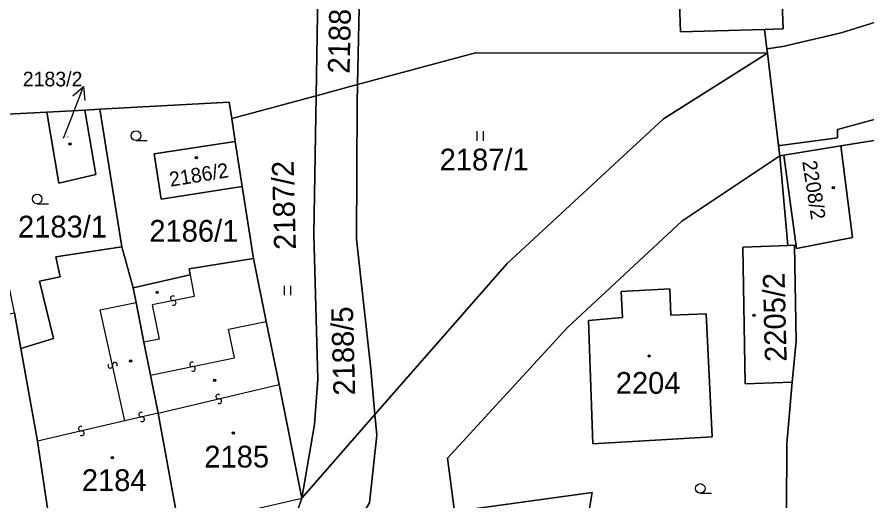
# Model space of a CAD drawing. Extents: x -596024 to -594475, y -1163820 to -1161957.
# Drawn here: x -595904.5 to -595838.1, y -1162929.2 to -1162891.5 of the extents above; entities that cross this region are included whole.
import ezdxf

# ---------------------------------------------------------------- set-up
doc = ezdxf.new("R2010")
doc.units = 0
for name, color, linetype in [('Level 1', 7, 'Continuous'), ('Level 13', 7, 'Continuous'), ('Level 3', 7, 'Continuous'), ('Level 4', 7, 'Continuous'), ('Level 5', 7, 'Continuous'), ('Level 57', 7, 'Continuous'), ('Level 60', 7, 'Continuous')]:
    doc.layers.add(name, color=color, linetype=linetype)

msp = doc.modelspace()

# ---------------------------------------------------------------- linework, layer by layer
at = {"layer": 'Level 1'}
for points in [[(-595689.67, -1162883.44), (-595700.86, -1162884.94), (-595711.82, -1162885.6), (-595719.78, -1162885.62), (-595739.76, -1162885.28), (-595774.42, -1162884.6), (-595796.1, -1162884.29), (-595801.08, -1162884.47), (-595808.03, -1162885.13), (-595817.92, -1162886.57), (-595821.84, -1162887.34), (-595827.71, -1162888.8), (-595840.08, -1162892.69), (-595844.64, -1162893.75), (-595845.9, -1162893.93)], [(-595846.86, -1162886.34), (-595844.86, -1162886.27), (-595844.63, -1162892.38), (-595846.09, -1162892.42)], [(-595846.09, -1162892.42), (-595852.65, -1162892.61), (-595852.84, -1162886.55), (-595846.86, -1162886.34)], [(-595880.94, -1162887.88), (-595880.94, -1162888.11), (-595881.1, -1162897.61)], [(-595877.88, -1162896.73), (-595877.69, -1162888.35)], [(-595845.9, -1162893.93), (-595846.09, -1162892.42)], [(-595844.98, -1162901.5), (-595844.85, -1162901.49), (-595840.38, -1162900.89), (-595840.38, -1162900.25), (-595836.17, -1162899.09), (-595829.54, -1162896.9), (-595823.17, -1162895.11), (-595816.86, -1162893.7), (-595811.96, -1162893.04)], [(-595845.85, -1162894.28), (-595868.65, -1162894.24), (-595877.88, -1162896.73)], [(-595845.85, -1162894.28), (-595845.9, -1162893.93)], [(-595876.51, -1162922.51), (-595866.18, -1162910.71), (-595853.97, -1162899.4), (-595845.85, -1162894.28)], [(-595844.98, -1162901.5), (-595845.85, -1162894.28)], [(-595877.88, -1162896.73), (-595881.1, -1162897.61)], [(-595876.51, -1162922.51), (-595876.84, -1162918.93), (-595877.95, -1162908.81), (-595877.91, -1162898.22), (-595877.88, -1162896.73)], [(-595898.01, -1162898.65), (-595887.89, -1162898.11), (-595887.69, -1162899.39)], [(-595881.1, -1162897.61), (-595887.69, -1162899.39)], [(-595881.1, -1162897.61), (-595881.28, -1162908.44), (-595880.98, -1162919.75), (-595881.22, -1162923.3), (-595882.23, -1162929.04)], [(-595902.15, -1162898.88), (-595907.82, -1162899.18)], [(-595902.15, -1162898.88), (-595901.19, -1162904.44), (-595898.3, -1162903.76), (-595899.18, -1162898.72)], [(-595899.18, -1162898.72), (-595902.15, -1162898.88)], [(-595898.01, -1162898.65), (-595899.18, -1162898.72)], [(-595898.01, -1162898.65), (-595896.28, -1162909.41)], [(-595840.12, -1162901.52), (-595822.87, -1162898.75)], [(-595887.42, -1162901.17), (-595887.69, -1162899.39)], [(-595886.87, -1162904.69), (-595893.2, -1162905.68), (-595893.75, -1162902.15), (-595887.42, -1162901.17)], [(-595887.42, -1162901.17), (-595886.87, -1162904.69)], [(-595844.88, -1162902.29), (-595844.98, -1162901.5)], [(-595844.56, -1162902.24), (-595840.12, -1162901.52)], [(-595840.12, -1162901.52), (-595839.22, -1162908.67), (-595843.59, -1162909.55), (-595844.56, -1162902.24)], [(-595844.88, -1162902.29), (-595844.56, -1162902.24)], [(-595844.88, -1162902.29), (-595852.53, -1162907.4), (-595861.47, -1162915.71), (-595870.83, -1162925.92), (-595870.3, -1162930.09), (-595859.54, -1162928.6), (-595860.31, -1162933.29), (-595852.92, -1162934.42), (-595851.41, -1162934.52)], [(-595844.27, -1162909.31), (-595844.88, -1162902.29)], [(-595886.87, -1162904.69), (-595886, -1162910.31)], [(-595896.28, -1162909.41), (-595901.43, -1162910.18), (-595901.1, -1162911.76), (-595902.72, -1162912.09), (-595901.62, -1162916.57), (-595904.16, -1162917.34)], [(-595895.4, -1162912.6), (-595896.28, -1162909.41)], [(-595843.91, -1162919.98), (-595847.58, -1162920.12), (-595847.77, -1162909.44), (-595844.27, -1162909.31)], [(-595843.91, -1162919.98), (-595843.62, -1162916.78), (-595843.75, -1162909.29), (-595844.27, -1162909.31)], [(-595886, -1162910.31), (-595891.03, -1162911.14), (-595890.95, -1162911.6)], [(-595885, -1162915.24), (-595886, -1162910.31)], [(-595895.4, -1162912.6), (-595890.95, -1162911.6)], [(-595895.17, -1162913.77), (-595895.4, -1162912.6)], [(-595859.84, -1162915.16), (-595859.49, -1162924.81), (-595850.18, -1162924.26), (-595850.63, -1162914.64), (-595853.39, -1162914.76), (-595853.48, -1162912.7), (-595857.27, -1162912.91), (-595857.18, -1162914.94), (-595859.84, -1162915.16)], [(-595894.55, -1162916.85), (-595895.17, -1162913.77)], [(-595904.66, -1162914.56), (-595904.16, -1162917.34)], [(-595883.99, -1162920.17), (-595885, -1162915.24)], [(-595904.16, -1162917.34), (-595902.86, -1162924.58)], [(-595894.03, -1162919.44), (-595894.55, -1162916.85)], [(-595893.43, -1162922.4), (-595894.03, -1162919.44)], [(-595843.91, -1162919.98), (-595844.34, -1162924.77), (-595844.4, -1162935.47)], [(-595883.99, -1162920.17), (-595882.23, -1162929.04)], [(-595892.11, -1162982.55), (-595893.66, -1162967.36), (-595893.27, -1162958.56), (-595891.77, -1162951.47), (-595888.99, -1162944.59), (-595880.96, -1162936.06), (-595876.94, -1162929.4), (-595876.36, -1162924.12), (-595876.51, -1162922.51)], [(-595893.43, -1162922.4), (-595891.83, -1162931.26)], [(-595876.51, -1162922.51), (-595882.23, -1162929.04)], [(-595901.53, -1162933.51), (-595902.86, -1162924.58)], [(-595882.57, -1162930.03), (-595882.23, -1162929.04)]]:
    msp.add_lwpolyline(points, dxfattribs=at)
at = {"layer": 'Level 13'}
for centre, start, end in [((-595892.295, -1162913.429), 48.23215, 280.82215), ((-595892.226, -1162913.791), 228.44661, 100.5446), ((-595897.18, -1162918.698), 139.85955, 11.95755), ((-595896.82, -1162918.621), 319.64509, 192.23509), ((-595890.796, -1162918.589), 49.01871, 281.11671), ((-595890.724, -1162918.95), 228.80425, 101.39425), ((-595888.751, -1162921.11), 50.66399, 282.76198), ((-595888.668, -1162921.469), 230.44953, 103.03953), ((-595894.78, -1162922.52), 50.10479, 282.69479), ((-595894.7, -1162922.88), 230.31924, 102.41724), ((-595899.491, -1162923.611), 50.20197, 282.79197), ((-595899.41, -1162923.97), 230.41643, 102.51442)]:
    msp.add_arc(centre, 0.184, start, end, dxfattribs=at)
at = {"layer": 'Level 3'}
for points in [[(-595890.95, -1162911.6), (-595890.63, -1162913.29), (-595893.9, -1162913.93), (-595893.37, -1162916.62), (-595894.55, -1162916.85)], [(-595896.04, -1162923), (-595897.96, -1162914.33), (-595895.17, -1162913.77)], [(-595894.03, -1162919.44), (-595887.48, -1162918.09), (-595887.94, -1162915.84), (-595885, -1162915.24)], [(-595893.43, -1162922.4), (-595883.99, -1162920.17)], [(-595893.43, -1162922.4), (-595896.04, -1162923)], [(-595896.04, -1162923), (-595902.86, -1162924.58)], [(-595891.83, -1162931.26), (-595882.23, -1162929.04)]]:
    msp.add_lwpolyline(points, dxfattribs=at)
at = {"layer": 'Level 5'}
for p, q in [((-595868.53, -1162901.115), (-595868.53, -1162900.364)), ((-595868.03, -1162901.115), (-595868.03, -1162900.364)), ((-595895.17, -1162901.1), (-595894.295, -1162901.1)), ((-595902.89, -1162906.04), (-595902.015, -1162906.04)), ((-595883.58, -1162913.195), (-595883.58, -1162912.444)), ((-595883.08, -1162913.195), (-595883.08, -1162912.444)), ((-595851.1, -1162928.66), (-595850.225, -1162928.66))]:
    msp.add_line(p, q, dxfattribs=at)
for centre, radius in [((-595895.17, -1162900.725), 0.375), ((-595900.32, -1162901.38), 0.09), ((-595900.32, -1162901.38), 0.0521), ((-595890.45, -1162902.45), 0.09), ((-595890.45, -1162902.45), 0.0521), ((-595840.71, -1162904.78), 0.09), ((-595840.71, -1162904.78), 0.0521), ((-595902.89, -1162905.665), 0.375), ((-595893.52, -1162912.96), 0.09), ((-595893.52, -1162912.96), 0.0521), ((-595846.9, -1162914.76), 0.09), ((-595846.9, -1162914.76), 0.0521), ((-595855.09, -1162917.93), 0.09), ((-595855.09, -1162917.93), 0.0521), ((-595895.59, -1162918.33), 0.09), ((-595895.59, -1162918.33), 0.0521), ((-595889.02, -1162919.85), 0.09), ((-595889.02, -1162919.85), 0.0521), ((-595887.58, -1162923.95), 0.09), ((-595887.58, -1162923.95), 0.0521), ((-595897.01, -1162925.89), 0.09), ((-595897.01, -1162925.89), 0.0521), ((-595851.1, -1162928.285), 0.375)]:
    msp.add_circle(centre, radius, dxfattribs=at)
at = {"layer": 'Level 57'}
for p, q in [((-595900.351, -1162899.669), (-595899.27, -1162896.87)), ((-595900.83, -1162900.91), (-595900.351, -1162899.669))]:
    msp.add_line(p, q, dxfattribs=at)
msp.add_lwpolyline([(-595900.097, -1162897.623), (-595899.27, -1162896.87), (-595899.164, -1162897.983)], dxfattribs=at)
at = {"layer": 'Level 60'}
for points in [[(-595880.94, -1162888.11), (-595881.1, -1162897.61), (-595887.69, -1162899.39), (-595887.89, -1162898.11), (-595898.01, -1162898.65), (-595899.18, -1162898.72), (-595902.15, -1162898.88), (-595907.82, -1162899.18), (-595923.48, -1162900.45), (-595934.83, -1162900.88), (-595942.06, -1162901.18), (-595961.43, -1162902), (-595966.37, -1162901.44), (-595978.21, -1162899.22), (-595980.89, -1162898.72), (-595991.69, -1162896.91), (-595991.71, -1162897.06), (-595998.18, -1162895.69), (-595999.71, -1162894.92), (-595997.34, -1162885.06)], [(-595827.71, -1162888.8), (-595840.08, -1162892.69), (-595844.64, -1162893.75), (-595845.9, -1162893.93), (-595846.09, -1162892.42), (-595844.63, -1162892.38), (-595844.86, -1162886.27)], [(-595836.17, -1162899.09), (-595840.38, -1162900.25), (-595840.38, -1162900.89), (-595844.85, -1162901.49), (-595844.98, -1162901.5), (-595845.85, -1162894.28), (-595845.9, -1162893.93), (-595844.64, -1162893.75), (-595840.08, -1162892.69), (-595827.71, -1162888.8)], [(-595876.94, -1162929.4), (-595876.36, -1162924.12), (-595876.51, -1162922.51), (-595866.18, -1162910.71), (-595853.97, -1162899.4), (-595845.85, -1162894.28), (-595844.98, -1162901.5), (-595844.88, -1162902.29), (-595852.53, -1162907.4), (-595861.47, -1162915.71), (-595870.83, -1162925.92), (-595870.3, -1162930.09), (-595859.54, -1162928.6), (-595860.31, -1162933.29)]]:
    msp.add_lwpolyline(points, dxfattribs=at)
for points in [[(-595852.84, -1162886.55), (-595852.65, -1162892.61), (-595846.09, -1162892.42), (-595845.9, -1162893.93), (-595845.85, -1162894.28), (-595868.65, -1162894.24), (-595877.88, -1162896.73), (-595877.69, -1162888.35), (-595846.93, -1162885.78), (-595846.86, -1162886.34)], [(-595852.65, -1162892.61), (-595852.84, -1162886.55), (-595846.86, -1162886.34), (-595844.86, -1162886.27), (-595844.63, -1162892.38), (-595846.09, -1162892.42)], [(-595880.94, -1162888.11), (-595880.94, -1162887.88), (-595877.66, -1162887.05), (-595877.69, -1162888.35), (-595877.88, -1162896.73), (-595881.1, -1162897.61)], [(-595844.85, -1162901.49), (-595840.38, -1162900.89), (-595840.38, -1162900.25), (-595836.17, -1162899.09), (-595829.54, -1162896.9), (-595823.17, -1162895.11), (-595816.86, -1162893.7), (-595811.96, -1162893.04), (-595811.88, -1162897.31), (-595822.87, -1162898.75), (-595840.12, -1162901.52), (-595844.56, -1162902.24), (-595844.88, -1162902.29), (-595844.98, -1162901.5)], [(-595853.97, -1162899.4), (-595866.18, -1162910.71), (-595876.51, -1162922.51), (-595876.84, -1162918.93), (-595877.95, -1162908.81), (-595877.91, -1162898.22), (-595877.88, -1162896.73), (-595868.65, -1162894.24), (-595845.85, -1162894.28)], [(-595880.98, -1162919.75), (-595881.28, -1162908.44), (-595881.1, -1162897.61), (-595877.88, -1162896.73), (-595877.91, -1162898.22), (-595877.95, -1162908.81), (-595876.84, -1162918.93), (-595876.51, -1162922.51), (-595882.23, -1162929.04), (-595881.22, -1162923.3)], [(-595896.28, -1162909.41), (-595898.01, -1162898.65), (-595887.89, -1162898.11), (-595887.69, -1162899.39), (-595887.42, -1162901.17), (-595893.75, -1162902.15), (-595893.2, -1162905.68), (-595886.87, -1162904.69), (-595886, -1162910.31), (-595891.03, -1162911.14), (-595890.95, -1162911.6), (-595895.4, -1162912.6)], [(-595881.28, -1162908.44), (-595880.98, -1162919.75), (-595881.22, -1162923.3), (-595882.23, -1162929.04), (-595883.99, -1162920.17), (-595885, -1162915.24), (-595886, -1162910.31), (-595886.87, -1162904.69), (-595887.42, -1162901.17), (-595887.69, -1162899.39), (-595881.1, -1162897.61)], [(-595904.16, -1162917.34), (-595904.66, -1162914.56), (-595907.82, -1162899.18), (-595902.15, -1162898.88), (-595901.19, -1162904.44), (-595898.3, -1162903.76), (-595899.18, -1162898.72), (-595898.01, -1162898.65), (-595896.28, -1162909.41), (-595901.43, -1162910.18), (-595901.1, -1162911.76), (-595902.72, -1162912.09), (-595901.62, -1162916.57)], [(-595901.19, -1162904.44), (-595902.15, -1162898.88), (-595899.18, -1162898.72), (-595898.3, -1162903.76)], [(-595822.36, -1162935.41), (-595844.4, -1162935.47), (-595844.34, -1162924.77), (-595843.91, -1162919.98), (-595843.62, -1162916.78), (-595843.75, -1162909.29), (-595844.27, -1162909.31), (-595844.88, -1162902.29), (-595844.56, -1162902.24), (-595843.59, -1162909.55), (-595839.22, -1162908.67), (-595840.12, -1162901.52), (-595822.87, -1162898.75), (-595822.76, -1162923.03), (-595822.37, -1162935.1)], [(-595893.2, -1162905.68), (-595893.75, -1162902.15), (-595887.42, -1162901.17), (-595886.87, -1162904.69)], [(-595840.12, -1162901.52), (-595839.22, -1162908.67), (-595843.59, -1162909.55), (-595844.56, -1162902.24)], [(-595847.58, -1162920.12), (-595843.91, -1162919.98), (-595844.34, -1162924.77), (-595844.4, -1162935.47), (-595851.41, -1162934.52), (-595852.92, -1162934.42), (-595860.31, -1162933.29), (-595859.54, -1162928.6), (-595870.3, -1162930.09), (-595870.83, -1162925.92), (-595861.47, -1162915.71), (-595852.53, -1162907.4), (-595844.88, -1162902.29), (-595844.27, -1162909.31), (-595847.77, -1162909.44)], [(-595901.53, -1162933.51), (-595902.86, -1162924.58), (-595904.16, -1162917.34), (-595901.62, -1162916.57), (-595902.72, -1162912.09), (-595901.1, -1162911.76), (-595901.43, -1162910.18), (-595896.28, -1162909.41), (-595895.4, -1162912.6), (-595895.17, -1162913.77), (-595894.55, -1162916.85), (-595894.03, -1162919.44), (-595893.43, -1162922.4), (-595891.83, -1162931.26), (-595891.12, -1162934.37), (-595901.08, -1162936.72)], [(-595843.91, -1162919.98), (-595847.58, -1162920.12), (-595847.77, -1162909.44), (-595844.27, -1162909.31), (-595843.75, -1162909.29), (-595843.62, -1162916.78)], [(-595882.57, -1162930.03), (-595885.98, -1162933.16), (-595891.12, -1162934.37), (-595891.83, -1162931.26), (-595893.43, -1162922.4), (-595894.03, -1162919.44), (-595894.55, -1162916.85), (-595895.17, -1162913.77), (-595895.4, -1162912.6), (-595890.95, -1162911.6), (-595891.03, -1162911.14), (-595886, -1162910.31), (-595885, -1162915.24), (-595883.99, -1162920.17), (-595882.23, -1162929.04)], [(-595859.84, -1162915.16), (-595859.49, -1162924.81), (-595850.18, -1162924.26), (-595850.63, -1162914.64), (-595853.39, -1162914.76), (-595853.48, -1162912.7), (-595857.27, -1162912.91), (-595857.18, -1162914.94)], [(-595859.49, -1162924.81), (-595859.84, -1162915.16), (-595857.18, -1162914.94), (-595857.27, -1162912.91), (-595853.48, -1162912.7), (-595853.39, -1162914.76), (-595850.63, -1162914.64), (-595850.18, -1162924.26)], [(-595917.65, -1162928.86), (-595919.1, -1162922.3), (-595919.29, -1162921.37), (-595920.21, -1162916.75), (-595910.13, -1162915.61), (-595904.66, -1162914.56), (-595904.16, -1162917.34), (-595902.86, -1162924.58), (-595901.53, -1162933.51), (-595915.71, -1162937.35)], [(-595876.94, -1162929.4), (-595880.96, -1162936.06), (-595888.99, -1162944.59), (-595891.77, -1162951.47), (-595893.27, -1162958.56), (-595893.66, -1162967.36), (-595892.11, -1162982.55), (-595891.41, -1162989.4), (-595901.8, -1162991.3), (-595899.15, -1162987.47), (-595897.33, -1162983.15), (-595896.94, -1162982.21), (-595896.78, -1162980.29), (-595897.62, -1162967.1), (-595897.31, -1162957.39), (-595895.91, -1162949.9), (-595892.65, -1162943.08), (-595887.94, -1162936.88), (-595885.92, -1162934.65), (-595882.99, -1162931.52), (-595882.57, -1162930.03), (-595882.23, -1162929.04), (-595876.51, -1162922.51), (-595876.36, -1162924.12)]]:
    msp.add_lwpolyline(points, close=True, dxfattribs=at)

# ---------------------------------------------------------------- texts
at = {"layer": 'Level 4'}
for s, height, rotation, p in [('2188/3', 1.7, 88.70112, (-595878.49, -1162895.888)), ('2186/2', 1.14, 9.3699, (-595892.472, -1162904.718)), ('2187/2', 1.7, 91.51947, (-595882.679, -1162909.617)), ('2208/2', 1.14, 278.85591, (-595843.138, -1162902.744)), ('2205/2', 1.7, 91.4382, (-595844.342, -1162918.376)), ('2188/5', 1.7, 91.51947, (-595878.048, -1162921.003))]:
    msp.add_text(s, height=height, rotation=rotation, dxfattribs=at).set_placement(p)
for s, height, p in [('2183/2', 0.1, (-595900.83, -1162900.91)), ('2187/1', 1.7, (-595871.456, -1162903.44)), ('2183/1', 1.7, (-595904.389, -1162908.68)), ('2186/1', 1.7, (-595894.132, -1162909.01)), ('2204', 1.7, (-595857.7, -1162920.89)), ('2185', 1.7, (-595889.835, -1162926.65)), ('2184', 1.7, (-595899.404, -1162928.49))]:
    msp.add_text(s, height=height, dxfattribs=at).set_placement(p)
at = {"layer": 'Level 57'}
msp.add_text('2183/2', height=1.14, dxfattribs=at).set_placement((-595904.018, -1162896.87))

doc.saveas('drawing.dxf')
